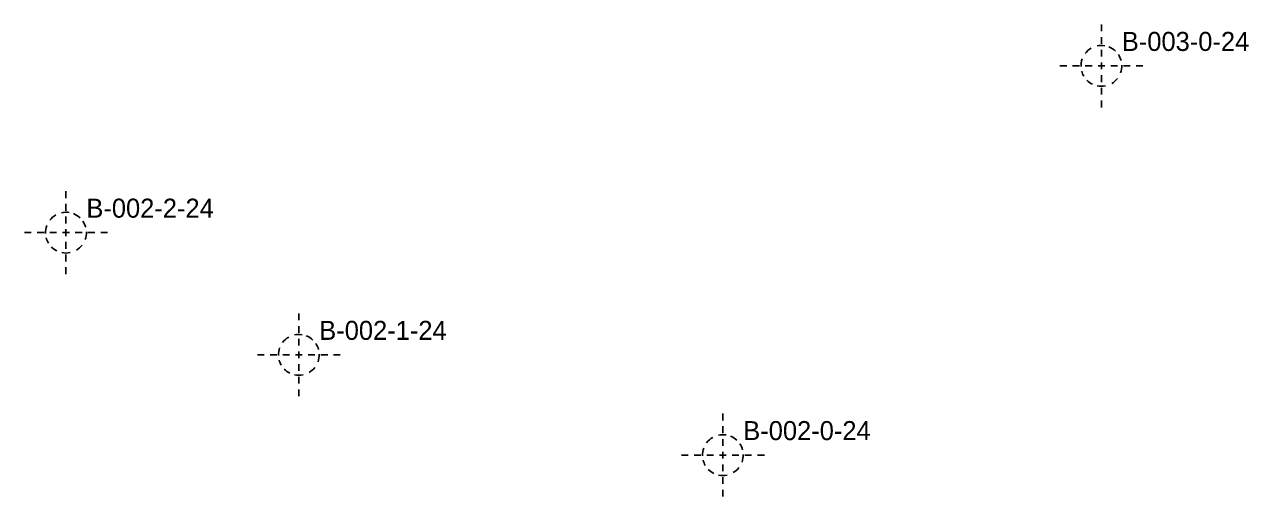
# Model space of a CAD drawing. Extents: x 144664 to 144883, y 371522 to 371728.
# Drawn here: x 144702.9 to 144882.8, y 371658.7 to 371728.2 of the extents above; entities that cross this region are included whole.
import ezdxf

# ---------------------------------------------------------------- set-up
doc = ezdxf.new("R2010")
doc.units = 0
doc.layers.add('GT_Historic_Soil_Boring', color=7, linetype='Continuous')
doc.layers.add('SH_Text', color=7, linetype='Continuous')

msp = doc.modelspace()

# ---------------------------------------------------------------- linework, layer by layer
at = {"layer": 'GT_Historic_Soil_Boring'}
for p, q in [((144861.16, 371727.18), (144861.16, 371728.18)), ((144861.16, 371727.18), (144861.16, 371728.18)), ((144861.16, 371725.31), (144861.16, 371726.31)), ((144861.16, 371725.31), (144861.16, 371726.31)), ((144861.16, 371723.44), (144861.16, 371724.44)), ((144861.16, 371723.44), (144861.16, 371724.44)), ((144855.06, 371722.08), (144856.06, 371722.08)), ((144855.06, 371722.08), (144856.06, 371722.08)), ((144856.93, 371722.08), (144857.93, 371722.08)), ((144856.93, 371722.08), (144857.93, 371722.08)), ((144858.79, 371722.08), (144859.79, 371722.08)), ((144858.79, 371722.08), (144859.79, 371722.08)), ((144860.66, 371722.08), (144861.66, 371722.08)), ((144860.66, 371722.08), (144861.66, 371722.08)), ((144861.16, 371721.58), (144861.16, 371722.58)), ((144861.16, 371721.58), (144861.16, 371722.58)), ((144862.53, 371722.08), (144863.53, 371722.08)), ((144862.53, 371722.08), (144863.53, 371722.08)), ((144864.39, 371722.08), (144865.39, 371722.08)), ((144864.39, 371722.08), (144865.39, 371722.08)), ((144866.26, 371722.08), (144867.26, 371722.08)), ((144866.26, 371722.08), (144867.26, 371722.08)), ((144861.16, 371719.71), (144861.16, 371720.71)), ((144861.16, 371719.71), (144861.16, 371720.71)), ((144861.16, 371717.85), (144861.16, 371718.85)), ((144861.16, 371717.85), (144861.16, 371718.85)), ((144861.16, 371715.98), (144861.16, 371716.98)), ((144861.16, 371715.98), (144861.16, 371716.98)), ((144708.95, 371702.64), (144708.95, 371703.64)), ((144708.95, 371702.64), (144708.95, 371703.64)), ((144708.95, 371700.78), (144708.95, 371701.78)), ((144708.95, 371700.78), (144708.95, 371701.78)), ((144708.95, 371698.91), (144708.95, 371699.91)), ((144708.95, 371698.91), (144708.95, 371699.91)), ((144708.95, 371697.05), (144708.95, 371698.05)), ((144708.95, 371697.05), (144708.95, 371698.05)), ((144702.85, 371697.55), (144703.85, 371697.55)), ((144702.85, 371697.55), (144703.85, 371697.55)), ((144704.72, 371697.55), (144705.72, 371697.55)), ((144704.72, 371697.55), (144705.72, 371697.55)), ((144706.58, 371697.55), (144707.58, 371697.55)), ((144706.58, 371697.55), (144707.58, 371697.55)), ((144708.45, 371697.55), (144709.45, 371697.55)), ((144708.45, 371697.55), (144709.45, 371697.55)), ((144708.95, 371695.18), (144708.95, 371696.18)), ((144708.95, 371695.18), (144708.95, 371696.18)), ((144710.32, 371697.55), (144711.32, 371697.55)), ((144710.32, 371697.55), (144711.32, 371697.55)), ((144712.18, 371697.55), (144713.18, 371697.55)), ((144712.18, 371697.55), (144713.18, 371697.55)), ((144714.05, 371697.55), (144715.05, 371697.55)), ((144714.05, 371697.55), (144715.05, 371697.55)), ((144708.95, 371693.31), (144708.95, 371694.31)), ((144708.95, 371693.31), (144708.95, 371694.31)), ((144708.95, 371691.45), (144708.95, 371692.45)), ((144708.95, 371691.45), (144708.95, 371692.45)), ((144743.18, 371684.67), (144743.18, 371685.67)), ((144743.18, 371684.67), (144743.18, 371685.67)), ((144743.18, 371682.8), (144743.18, 371683.8)), ((144743.18, 371682.8), (144743.18, 371683.8)), ((144743.18, 371680.93), (144743.18, 371681.93)), ((144743.18, 371680.93), (144743.18, 371681.93)), ((144743.18, 371679.07), (144743.18, 371680.07)), ((144743.18, 371679.07), (144743.18, 371680.07)), ((144737.08, 371679.57), (144738.08, 371679.57)), ((144737.08, 371679.57), (144738.08, 371679.57)), ((144738.95, 371679.57), (144739.95, 371679.57)), ((144738.95, 371679.57), (144739.95, 371679.57)), ((144740.82, 371679.57), (144741.82, 371679.57)), ((144740.82, 371679.57), (144741.82, 371679.57)), ((144742.68, 371679.57), (144743.68, 371679.57)), ((144742.68, 371679.57), (144743.68, 371679.57)), ((144743.18, 371677.2), (144743.18, 371678.2)), ((144743.18, 371677.2), (144743.18, 371678.2)), ((144744.55, 371679.57), (144745.55, 371679.57)), ((144744.55, 371679.57), (144745.55, 371679.57)), ((144746.42, 371679.57), (144747.42, 371679.57)), ((144746.42, 371679.57), (144747.42, 371679.57)), ((144748.28, 371679.57), (144749.28, 371679.57)), ((144748.28, 371679.57), (144749.28, 371679.57)), ((144743.18, 371675.34), (144743.18, 371676.34)), ((144743.18, 371675.34), (144743.18, 371676.34)), ((144743.18, 371673.47), (144743.18, 371674.47)), ((144743.18, 371673.47), (144743.18, 371674.47)), ((144805.51, 371669.92), (144805.51, 371670.92)), ((144805.51, 371669.92), (144805.51, 371670.92)), ((144805.51, 371668.05), (144805.51, 371669.05)), ((144805.51, 371668.05), (144805.51, 371669.05)), ((144805.51, 371666.18), (144805.51, 371667.18)), ((144805.51, 371666.18), (144805.51, 371667.18)), ((144799.41, 371664.82), (144800.41, 371664.82)), ((144799.41, 371664.82), (144800.41, 371664.82)), ((144801.28, 371664.82), (144802.28, 371664.82)), ((144801.28, 371664.82), (144802.28, 371664.82)), ((144803.14, 371664.82), (144804.14, 371664.82)), ((144803.14, 371664.82), (144804.14, 371664.82)), ((144805.01, 371664.82), (144806.01, 371664.82)), ((144805.01, 371664.82), (144806.01, 371664.82)), ((144805.51, 371664.32), (144805.51, 371665.32)), ((144805.51, 371664.32), (144805.51, 371665.32)), ((144806.87, 371664.82), (144807.87, 371664.82)), ((144806.87, 371664.82), (144807.87, 371664.82)), ((144808.74, 371664.82), (144809.74, 371664.82)), ((144808.74, 371664.82), (144809.74, 371664.82)), ((144810.61, 371664.82), (144811.61, 371664.82)), ((144810.61, 371664.82), (144811.61, 371664.82)), ((144805.51, 371662.45), (144805.51, 371663.45)), ((144805.51, 371662.45), (144805.51, 371663.45)), ((144805.51, 371660.58), (144805.51, 371661.58)), ((144805.51, 371660.58), (144805.51, 371661.58)), ((144805.51, 371658.72), (144805.51, 371659.72)), ((144805.51, 371658.72), (144805.51, 371659.72))]:
    msp.add_line(p, q, dxfattribs=at)
for centre, start, end in [((144861.16, 371722.08), 80.7068, 102.4607), ((144861.16, 371722.08), 80.7068, 102.4607), ((144861.16, 371722.08), 160.0066, 182.1314), ((144861.16, 371722.08), 160.0066, 182.1314), ((144861.16, 371722.08), 119.8468, 142.879), ((144861.16, 371722.08), 119.8468, 142.879), ((144861.16, 371722.08), 46.3828, 68.4543), ((144861.16, 371722.08), 46.3828, 68.4543), ((144861.16, 371722.08), 15.179, 33.755), ((144861.16, 371722.08), 15.179, 33.755), ((144861.16, 371722.08), 194.7234, 210.6686), ((144861.16, 371722.08), 194.7234, 210.6686), ((144861.16, 371722.08), 339.9977, 1.8728), ((144861.16, 371722.08), 339.9977, 1.8728), ((144861.16, 371722.08), 224.4987, 243.6713), ((144861.16, 371722.08), 224.4987, 243.6713), ((144861.16, 371722.08), 300.6921, 322.0293), ((144861.16, 371722.08), 300.6921, 322.0293), ((144861.16, 371722.08), 257.8817, 281.9218), ((144861.16, 371722.08), 257.8817, 281.9218), ((144708.95, 371697.55), 119.8468, 142.879), ((144708.95, 371697.55), 119.8468, 142.879), ((144708.95, 371697.55), 80.7068, 102.4607), ((144708.95, 371697.55), 80.7068, 102.4607), ((144708.95, 371697.55), 46.3828, 68.4543), ((144708.95, 371697.55), 46.3828, 68.4543), ((144708.95, 371697.55), 160.0066, 182.1314), ((144708.95, 371697.55), 160.0066, 182.1314), ((144708.95, 371697.55), 15.179, 33.755), ((144708.95, 371697.55), 15.179, 33.755), ((144708.95, 371697.55), 194.7234, 210.6686), ((144708.95, 371697.55), 194.7234, 210.6686), ((144708.95, 371697.55), 339.9977, 1.8728), ((144708.95, 371697.55), 339.9977, 1.8728), ((144708.95, 371697.55), 224.4987, 243.6713), ((144708.95, 371697.55), 224.4987, 243.6713), ((144708.95, 371697.55), 257.8817, 281.9218), ((144708.95, 371697.55), 257.8817, 281.9218), ((144708.95, 371697.55), 300.6921, 322.0293), ((144708.95, 371697.55), 300.6921, 322.0293), ((144743.18, 371679.57), 119.8468, 142.879), ((144743.18, 371679.57), 119.8468, 142.879), ((144743.18, 371679.57), 80.7068, 102.4607), ((144743.18, 371679.57), 80.7068, 102.4607), ((144743.18, 371679.57), 46.3828, 68.4543), ((144743.18, 371679.57), 46.3828, 68.4543), ((144743.18, 371679.57), 160.0066, 182.1314), ((144743.18, 371679.57), 160.0066, 182.1314), ((144743.18, 371679.57), 15.179, 33.755), ((144743.18, 371679.57), 15.179, 33.755), ((144743.18, 371679.57), 194.7234, 210.6686), ((144743.18, 371679.57), 194.7234, 210.6686), ((144743.18, 371679.57), 339.9977, 1.8728), ((144743.18, 371679.57), 339.9977, 1.8728), ((144743.18, 371679.57), 224.4987, 243.6713), ((144743.18, 371679.57), 224.4987, 243.6713), ((144743.18, 371679.57), 257.8817, 281.9218), ((144743.18, 371679.57), 257.8817, 281.9218), ((144743.18, 371679.57), 300.6921, 322.0293), ((144743.18, 371679.57), 300.6921, 322.0293), ((144805.51, 371664.82), 119.8468, 142.879), ((144805.51, 371664.82), 119.8468, 142.879), ((144805.51, 371664.82), 80.7068, 102.4607), ((144805.51, 371664.82), 80.7068, 102.4607), ((144805.51, 371664.82), 46.3828, 68.4543), ((144805.51, 371664.82), 46.3828, 68.4543), ((144805.51, 371664.82), 160.0066, 182.1314), ((144805.51, 371664.82), 160.0066, 182.1314), ((144805.51, 371664.82), 15.179, 33.755), ((144805.51, 371664.82), 15.179, 33.755), ((144805.51, 371664.82), 194.7234, 210.6686), ((144805.51, 371664.82), 194.7234, 210.6686), ((144805.51, 371664.82), 339.9977, 1.8728), ((144805.51, 371664.82), 339.9977, 1.8728), ((144805.51, 371664.82), 224.4987, 243.6713), ((144805.51, 371664.82), 224.4987, 243.6713), ((144805.51, 371664.82), 300.6921, 322.0293), ((144805.51, 371664.82), 300.6921, 322.0293), ((144805.51, 371664.82), 257.8817, 281.9218), ((144805.51, 371664.82), 257.8817, 281.9218)]:
    msp.add_arc(centre, 3, start, end, dxfattribs=at)

# ---------------------------------------------------------------- texts
at = {"layer": 'SH_Text'}
for s, p in [('B-003-0-24', (144864.16, 371724.28)), ('B-002-2-24', (144711.95, 371699.75)), ('B-002-1-24', (144746.18, 371681.77)), ('B-002-0-24', (144808.51, 371667.02))]:
    msp.add_text(s, height=2.8, dxfattribs=at).set_placement(p)

doc.saveas('drawing.dxf')
